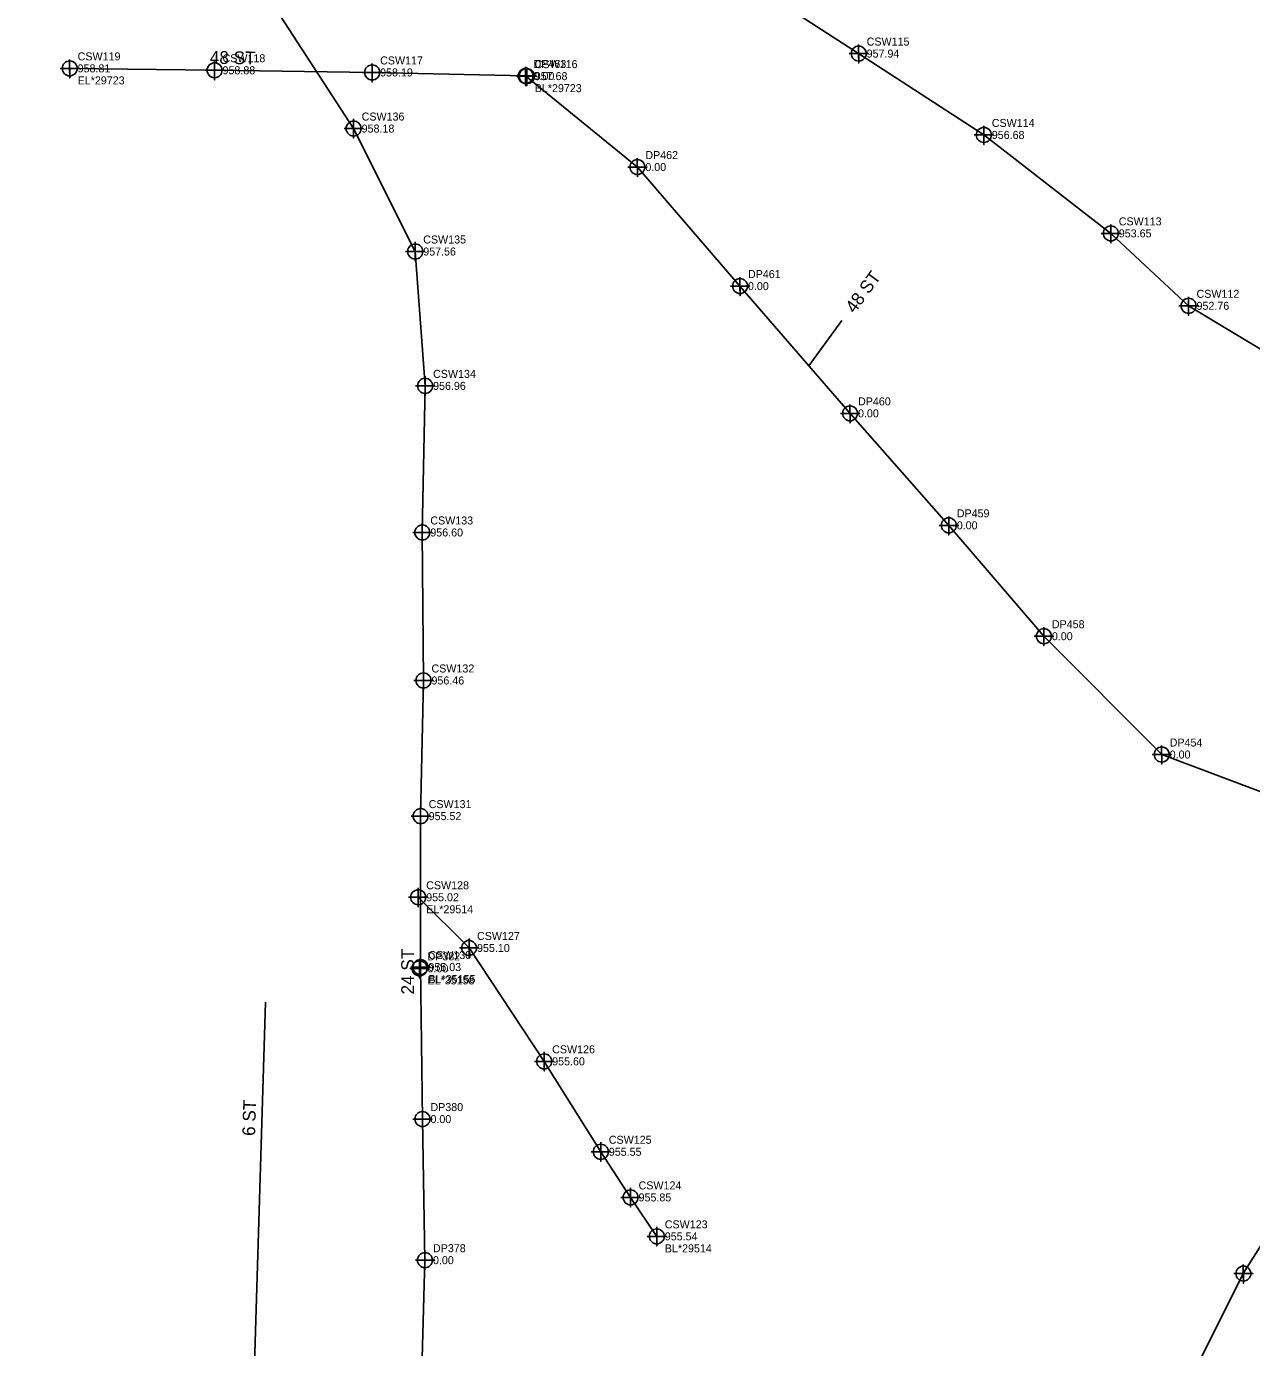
# Model space of a CAD drawing. Extents: x 1182504 to 1186036, y 573002 to 575111.
# Drawn here: x 1183757 to 1184140, y 573570.7 to 573983.4 of the extents above; entities that cross this region are included whole.
import ezdxf

# ---------------------------------------------------------------- set-up
doc = ezdxf.new("R2010")
doc.units = 0
for name, color, linetype in [('Exist Utilities Power UG Cable SUE LOS B', 7, 'Continuous'), ('Exist Utilities Power UG Cable SUE LOS B Cogo Comment', 7, 'Continuous'), ('Exist Utilities Power UG Cable SUE LOS B Cogo Elevation', 7, 'Continuous'), ('Exist Utilities Power UG Cable SUE LOS B Cogo Number', 7, 'Continuous'), ('Exist Utilities Power UG Cable SUE LOS B Cogo Point CELL', 7, 'Continuous'), ('Exist Utilities Telephone UG Conduit SUE LOS B', 7, 'Continuous'), ('Exist Utilities Telephone UG Conduit SUE LOS B Cogo Comment', 7, 'Continuous'), ('Exist Utilities Telephone UG Conduit SUE LOS B Cogo Elevation', 7, 'Continuous'), ('Exist Utilities Telephone UG Conduit SUE LOS B Cogo Number', 7, 'Continuous'), ('Exist Utilities Telephone UG Conduit SUE LOS B Cogo Point CELL', 7, 'Continuous'), ('Exist Utilities Telephone UG Conduit SUE LOS B Leader', 7, 'Continuous'), ('Exist Utilities Telephone UG Conduit SUE LOS B Text', 7, 'Continuous'), ('Exist Utilities Telephone UG FO SUE LOS C', 7, 'Continuous'), ('Exist Utilities Telephone UG FO SUE LOS C Cogo Comment', 7, 'Continuous'), ('Exist Utilities Telephone UG FO SUE LOS C Cogo Elevation', 7, 'Continuous'), ('Exist Utilities Telephone UG FO SUE LOS C Cogo Number', 7, 'Continuous'), ('Exist Utilities Telephone UG FO SUE LOS C Cogo Point CELL', 7, 'Continuous'), ('Exist Utilities Telephone UG FO SUE LOS C Text', 7, 'Continuous')]:
    doc.layers.add(name, color=color, linetype=linetype)

msp = doc.modelspace()

# ---------------------------------------------------------------- linework, layer by layer
at = {"layer": 'Exist Utilities Power UG Cable SUE LOS B'}
msp.add_lwpolyline([(1183954.03, 573605.4), (1183945.83, 573617.57), (1183936.53, 573631.83), (1183918.82, 573660.08), (1183895.33, 573695.5), (1183879.44, 573711.34)], dxfattribs=at)
at = {"layer": 'Exist Utilities Power UG Cable SUE LOS B Cogo Point CELL'}
for points in [[(1183879.44, 573714.34), (1183879.44, 573708.34), (1183879.44, 573711.34), (1183882.44, 573711.34), (1183876.44, 573711.34)], [(1183895.33, 573698.5), (1183895.33, 573692.5), (1183895.33, 573695.5), (1183898.33, 573695.5), (1183892.33, 573695.5)], [(1183918.82, 573663.08), (1183918.82, 573657.08), (1183918.82, 573660.08), (1183921.82, 573660.08), (1183915.82, 573660.08)], [(1183936.53, 573634.83), (1183936.53, 573628.83), (1183936.53, 573631.83), (1183939.53, 573631.83), (1183933.53, 573631.83)], [(1183945.83, 573620.57), (1183945.83, 573614.57), (1183945.83, 573617.57), (1183948.83, 573617.57), (1183942.83, 573617.57)], [(1183954.03, 573608.4), (1183954.03, 573602.4), (1183954.03, 573605.4), (1183957.03, 573605.4), (1183951.03, 573605.4)]]:
    msp.add_lwpolyline(points, dxfattribs=at)
for centre in [(1183879.44, 573711.34), (1183895.33, 573695.5), (1183918.82, 573660.08), (1183936.53, 573631.83), (1183945.83, 573617.57), (1183954.03, 573605.4)]:
    msp.add_circle(centre, 2.34, dxfattribs=at)
at = {"layer": 'Exist Utilities Telephone UG Conduit SUE LOS B'}
for points in [[(1183461.9, 574217.61), (1183507.97, 574205.1), (1183555.78, 574190.97), (1183600.29, 574174.7), (1183642.38, 574158.78), (1183685.83, 574141.54), (1183729.44, 574124.53), (1183772.61, 574105.48), (1183815.48, 574084.72), (1183856.9, 574064.89), (1183910.26, 574040.72), (1183938.65, 574025.64), (1184017.13, 573974.93), (1184056.25, 573949.51), (1184095.95, 573918.75), (1184120.25, 573896.12), (1184153.18, 573876.37), (1184177.6, 573863.32)], [(1183913, 573967.93), (1183865.04, 573969.03), (1183815.77, 573969.72), (1183770.48, 573970.3)], [(1184210.63, 573717.89), (1184181.04, 573731.42), (1184150.69, 573741.38), (1184111.86, 573755.94), (1184075.03, 573792.9), (1184045.3, 573827.54), (1184014.43, 573862.52), (1183980.03, 573902.29), (1183947.95, 573939.47), (1183913, 573967.93)], [(1184020.78, 573306.4), (1183988.14, 573330.66), (1183985.98, 573336.24), (1183991.53, 573344.95), (1184017.37, 573382.34), (1184043.22, 573419.6), (1184071.03, 573458.88), (1184092.18, 573492.71), (1184101.38, 573521.29), (1184118.41, 573555.81), (1184137.37, 573593.76), (1184158.33, 573627.01), (1184186.36, 573674.25), (1184210.73, 573715)]]:
    msp.add_lwpolyline(points, dxfattribs=at)
at = {"layer": 'Exist Utilities Telephone UG Conduit SUE LOS B Cogo Point CELL'}
for points in [[(1184017.11, 573977.75), (1184017.14, 573971.93), (1184017.13, 573974.93), (1184020.14, 573974.93), (1184014.14, 573974.93)], [(1183770.46, 573973.11), (1183770.5, 573967.3), (1183770.48, 573970.3), (1183773.5, 573970.3), (1183767.5, 573970.3)], [(1183815.76, 573972.54), (1183815.79, 573966.72), (1183815.77, 573969.72), (1183818.79, 573969.72), (1183812.79, 573969.72)], [(1183865.02, 573971.84), (1183865.05, 573966.03), (1183865.04, 573969.03), (1183868.05, 573969.03), (1183862.05, 573969.03)], [(1183912.98, 573970.74), (1183913.02, 573964.93), (1183913, 573967.93), (1183916.02, 573967.93), (1183910.02, 573967.93)], [(1183913.35, 573970.69), (1183913.39, 573964.87), (1183913.37, 573967.87), (1183916.39, 573967.87), (1183910.39, 573967.87)], [(1184056.24, 573952.33), (1184056.27, 573946.51), (1184056.25, 573949.51), (1184059.27, 573949.51), (1184053.27, 573949.51)], [(1183947.93, 573942.29), (1183947.97, 573936.47), (1183947.95, 573939.47), (1183950.97, 573939.47), (1183944.97, 573939.47)], [(1184095.94, 573921.57), (1184095.97, 573915.75), (1184095.95, 573918.75), (1184098.97, 573918.75), (1184092.97, 573918.75)], [(1183980.01, 573905.11), (1183980.04, 573899.29), (1183980.03, 573902.29), (1183983.04, 573902.29), (1183977.04, 573902.29)], [(1184120.23, 573898.93), (1184120.27, 573893.12), (1184120.25, 573896.12), (1184123.27, 573896.12), (1184117.27, 573896.12)], [(1184014.41, 573865.34), (1184014.44, 573859.52), (1184014.43, 573862.52), (1184017.44, 573862.52), (1184011.44, 573862.52)], [(1184045.28, 573830.35), (1184045.31, 573824.54), (1184045.3, 573827.54), (1184048.31, 573827.54), (1184042.31, 573827.54)], [(1184075.01, 573795.71), (1184075.04, 573789.9), (1184075.03, 573792.9), (1184078.04, 573792.9), (1184072.04, 573792.9)], [(1184111.85, 573758.76), (1184111.88, 573752.94), (1184111.86, 573755.94), (1184114.88, 573755.94), (1184108.88, 573755.94)], [(1184137.36, 573596.57), (1184137.39, 573590.76), (1184137.37, 573593.76), (1184140.39, 573593.76), (1184134.39, 573593.76)]]:
    msp.add_lwpolyline(points, dxfattribs=at)
for centre in [(1184017.14, 573974.93), (1183770.5, 573970.3), (1183815.79, 573969.72), (1183865.05, 573969.03), (1183913.02, 573967.93), (1183913.39, 573967.87), (1184056.27, 573949.51), (1183947.97, 573939.47), (1184095.97, 573918.75), (1183980.04, 573902.29), (1184120.27, 573896.12), (1184014.44, 573862.52), (1184045.31, 573827.54), (1184075.04, 573792.9), (1184111.88, 573755.94), (1184137.39, 573593.76)]:
    msp.add_circle(centre, 2.34, dxfattribs=at)
at = {"layer": 'Exist Utilities Telephone UG Conduit SUE LOS B Leader'}
msp.add_line((1184001.57, 573877.39), (1184011.87, 573891.52), dxfattribs=at)
at = {"layer": 'Exist Utilities Telephone UG FO SUE LOS C'}
for points in [[(1183880.14, 573689.54), (1183880.21, 573736.69), (1183881.09, 573779.07), (1183880.73, 573825.31), (1183881.6, 573871.11), (1183878.51, 573913.09), (1183859.26, 573951.5), (1183833.73, 573990.76), (1183813.35, 574023.89), (1183792.16, 574060.17), (1183766.16, 574102.11)], [(1183831.2, 573051.4), (1183831.99, 573067.67), (1183835.94, 573100.34), (1183843.81, 573135.41), (1183849.42, 573158.28), (1183872.21, 573240.17), (1183881.95, 573271.33), (1183882.59, 573295.88), (1183881.95, 573329.75), (1183881.17, 573370.19), (1183880.74, 573416.08), (1183881.11, 573461.73), (1183880.38, 573505.49), (1183880.23, 573552), (1183881.56, 573597.96), (1183880.77, 573642.04), (1183880.14, 573689.54)], [(1183763.45, 573220.41), (1183819.5, 573277.67), (1183831.72, 573678.52)]]:
    msp.add_lwpolyline(points, dxfattribs=at)
at = {"layer": 'Exist Utilities Telephone UG FO SUE LOS C Cogo Point CELL'}
for points in [[(1183859.26, 573954.5), (1183859.26, 573948.5), (1183859.26, 573951.5), (1183862.26, 573951.5), (1183856.26, 573951.5)], [(1183878.51, 573916.09), (1183878.51, 573910.09), (1183878.51, 573913.09), (1183881.51, 573913.09), (1183875.51, 573913.09)], [(1183881.6, 573874.11), (1183881.6, 573868.11), (1183881.6, 573871.11), (1183884.6, 573871.11), (1183878.6, 573871.11)], [(1183880.73, 573828.31), (1183880.73, 573822.31), (1183880.73, 573825.31), (1183883.73, 573825.31), (1183877.73, 573825.31)], [(1183881.09, 573782.07), (1183881.09, 573776.07), (1183881.09, 573779.07), (1183884.09, 573779.07), (1183878.09, 573779.07)], [(1183880.21, 573739.69), (1183880.21, 573733.69), (1183880.21, 573736.69), (1183883.21, 573736.69), (1183877.21, 573736.69)], [(1183879.85, 573692.12), (1183879.85, 573686.12), (1183879.85, 573689.12), (1183882.85, 573689.12), (1183876.85, 573689.12)], [(1183880.14, 573692.54), (1183880.14, 573686.54), (1183880.14, 573689.54), (1183883.14, 573689.54), (1183877.14, 573689.54)], [(1183880.77, 573645.04), (1183880.77, 573639.04), (1183880.77, 573642.04), (1183883.77, 573642.04), (1183877.77, 573642.04)], [(1183881.56, 573600.96), (1183881.56, 573594.96), (1183881.56, 573597.96), (1183884.56, 573597.96), (1183878.56, 573597.96)]]:
    msp.add_lwpolyline(points, dxfattribs=at)
for centre in [(1183859.26, 573951.5), (1183878.51, 573913.09), (1183881.6, 573871.11), (1183880.73, 573825.31), (1183881.09, 573779.07), (1183880.21, 573736.69), (1183879.85, 573689.12), (1183880.14, 573689.54), (1183880.77, 573642.04), (1183881.56, 573597.96)]:
    msp.add_circle(centre, 2.34, dxfattribs=at)

# ---------------------------------------------------------------- texts
at = {"layer": 'Exist Utilities Power UG Cable SUE LOS B Cogo Comment'}
for s, p in [('EL*29514', (1183881.94, 573706.34)), ('BL*29514', (1183956.53, 573600.4))]:
    msp.add_text(s, height=2.5, dxfattribs=at).set_placement(p)
at = {"layer": 'Exist Utilities Power UG Cable SUE LOS B Cogo Elevation'}
for s, p in [('955.02', (1183881.94, 573710.09)), ('955.10', (1183897.83, 573694.25)), ('955.60', (1183921.32, 573658.83)), ('955.55', (1183939.03, 573630.58)), ('955.85', (1183948.33, 573616.32)), ('955.54', (1183956.53, 573604.15))]:
    msp.add_text(s, height=2.5, dxfattribs=at).set_placement(p)
at = {"layer": 'Exist Utilities Power UG Cable SUE LOS B Cogo Number'}
for s, p in [('CSW128', (1183881.94, 573713.84)), ('CSW127', (1183897.83, 573698)), ('CSW126', (1183921.32, 573662.58)), ('CSW125', (1183939.03, 573634.33)), ('CSW124', (1183948.33, 573620.07)), ('CSW123', (1183956.53, 573607.9))]:
    msp.add_text(s, height=2.5, dxfattribs=at).set_placement(p)
at = {"layer": 'Exist Utilities Telephone UG Conduit SUE LOS B Cogo Comment'}
for s, p in [('EL*29723', (1183772.98, 573965.3)), ('BL*29723', (1183915.87, 573962.87))]:
    msp.add_text(s, height=2.5, dxfattribs=at).set_placement(p)
at = {"layer": 'Exist Utilities Telephone UG Conduit SUE LOS B Cogo Elevation'}
for s, p in [('957.94', (1184019.63, 573973.68)), ('958.81', (1183772.98, 573969.05)), ('958.88', (1183818.27, 573968.47)), ('958.19', (1183867.54, 573967.78)), ('0.00', (1183915.5, 573966.68)), ('957.68', (1183915.87, 573966.62)), ('956.68', (1184058.75, 573948.26)), ('0.00', (1183950.45, 573938.22)), ('953.65', (1184098.45, 573917.5)), ('0.00', (1183982.53, 573901.04)), ('952.76', (1184122.75, 573894.87)), ('0.00', (1184016.93, 573861.27)), ('0.00', (1184047.8, 573826.29)), ('0.00', (1184077.53, 573791.65)), ('0.00', (1184114.36, 573754.69))]:
    msp.add_text(s, height=2.5, dxfattribs=at).set_placement(p)
at = {"layer": 'Exist Utilities Telephone UG Conduit SUE LOS B Cogo Number'}
for s, p in [('CSW115', (1184019.63, 573977.43)), ('CSW119', (1183772.98, 573972.8)), ('CSW118', (1183818.27, 573972.22)), ('CSW117', (1183867.54, 573971.53)), ('DP463', (1183915.5, 573970.43)), ('CSW116', (1183915.87, 573970.37)), ('CSW114', (1184058.75, 573952.01)), ('DP462', (1183950.45, 573941.97)), ('CSW113', (1184098.45, 573921.25)), ('DP461', (1183982.53, 573904.79)), ('CSW112', (1184122.75, 573898.62)), ('DP460', (1184016.93, 573865.02)), ('DP459', (1184047.8, 573830.04)), ('DP458', (1184077.53, 573795.4)), ('DP454', (1184114.36, 573758.44))]:
    msp.add_text(s, height=2.5, dxfattribs=at).set_placement(p)
at = {"layer": 'Exist Utilities Telephone UG Conduit SUE LOS B Text'}
for rotation, p in [(359.1877, (1183814.28, 573971.75)), (53.9157, (1184015.88, 573893.55))]:
    msp.add_text('48 ST', height=4, rotation=rotation, dxfattribs=at).set_placement(p)
at = {"layer": 'Exist Utilities Telephone UG FO SUE LOS C Cogo Comment'}
for s, p in [('EL*35158', (1183882.35, 573684.12)), ('BL*35155', (1183882.64, 573684.54))]:
    msp.add_text(s, height=2.5, dxfattribs=at).set_placement(p)
at = {"layer": 'Exist Utilities Telephone UG FO SUE LOS C Cogo Elevation'}
for s, p in [('958.18', (1183861.76, 573950.25)), ('957.56', (1183881.01, 573911.84)), ('956.96', (1183884.1, 573869.86)), ('956.60', (1183883.23, 573824.06)), ('956.46', (1183883.59, 573777.82)), ('955.52', (1183882.71, 573735.44)), ('0.00', (1183882.35, 573687.87)), ('955.03', (1183882.64, 573688.29)), ('0.00', (1183883.27, 573640.79)), ('0.00', (1183884.06, 573596.71))]:
    msp.add_text(s, height=2.5, dxfattribs=at).set_placement(p)
at = {"layer": 'Exist Utilities Telephone UG FO SUE LOS C Cogo Number'}
for s, p in [('CSW136', (1183861.76, 573954)), ('CSW135', (1183881.01, 573915.59)), ('CSW134', (1183884.1, 573873.61)), ('CSW133', (1183883.23, 573827.81)), ('CSW132', (1183883.59, 573781.57)), ('CSW131', (1183882.71, 573739.19)), ('DP382', (1183882.35, 573691.62)), ('CSW130', (1183882.64, 573692.04)), ('DP380', (1183883.27, 573644.54)), ('DP378', (1183884.06, 573600.46))]:
    msp.add_text(s, height=2.5, dxfattribs=at).set_placement(p)
at = {"layer": 'Exist Utilities Telephone UG FO SUE LOS C Text'}
for s, rotation, p in [('24 ST', 89.9254, (1183878.13, 573680.98)), ('6 ST', 88.2533, (1183828.44, 573636.74))]:
    msp.add_text(s, height=4, rotation=rotation, dxfattribs=at).set_placement(p)

doc.saveas('drawing.dxf')
